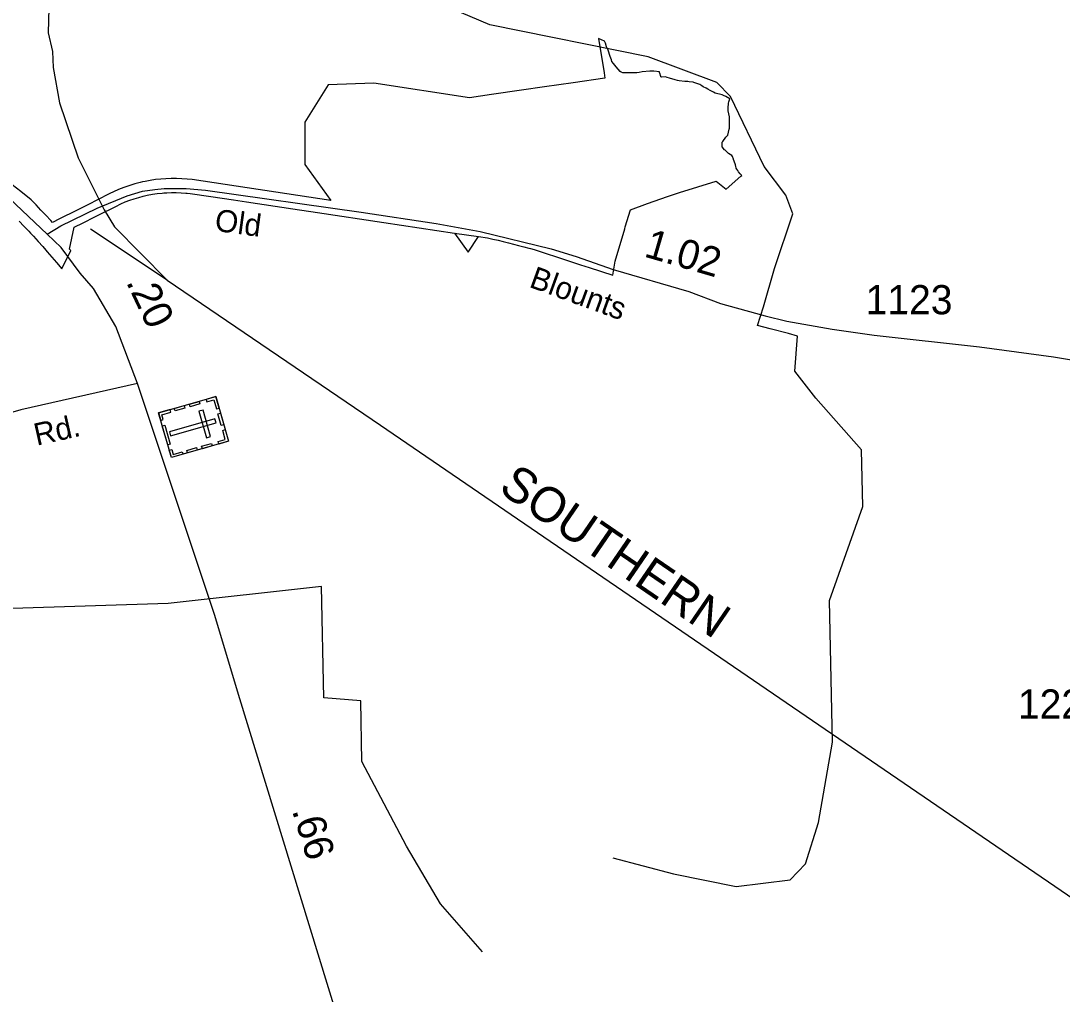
# Model space of a CAD drawing. Extents: x 2532689 to 2764727, y 536648 to 732970.
# Drawn here: x 2571899 to 2576359, y 639225 to 643394 of the extents above; entities that cross this region are included whole.
import ezdxf

# ---------------------------------------------------------------- set-up
doc = ezdxf.new("R2010")
doc.units = 0
for name, color, linetype in [('Exist Boundary Political City Limit New', 7, 'Continuous'), ('Exist Cultural Cemetery CELL', 7, 'Continuous'), ('Exist Hydrographic Creek Single Shore', 7, 'Continuous'), ('Exist Railroad Mainline', 7, 'Continuous'), ('Exist Railroad Mainline Label', 7, 'Continuous'), ('Exist Railroad Siding', 7, 'Continuous'), ('Exist Road Primary NC Attributed', 7, 'Continuous'), ('Exist Road Primary NC Mileage Hundredths English Label', 7, 'Continuous'), ('Exist Road Secondary Mileage Hundredths English Label', 7, 'Continuous'), ('Exist Road Secondary Type 51 Attributed', 7, 'Continuous'), ('Exist Road Secondary Type 51 Label', 7, 'Continuous'), ('Exist Road Secondary Type 51 Number Label', 7, 'Continuous'), ('Map Preparation Boundary City Limit Buffer Line', 7, 'Continuous')]:
    doc.layers.add(name, color=color, linetype=linetype)

msp = doc.modelspace()

# ---------------------------------------------------------------- linework, layer by layer
at = {"layer": 'Exist Boundary Political City Limit New'}
for points in [[(2574743.5, 643134.7), (2574718.8, 643136.3), (2574711, 643138.3), (2574702, 643141.1), (2574677, 643148.3), (2574667, 643151.5), (2574660.8, 643153.9), (2574644, 643153.1), (2574640.2, 643153.9), (2574639.8, 643155.4), (2574636.2, 643169.1), (2574635, 643171.5), (2574634.2, 643175.9), (2574610.2, 643177.9), (2574592.8, 643178.3), (2574560, 643175.1), (2574546.8, 643172.3), (2574537.8, 643171.5), (2574501.5, 643170.8), (2574495.5, 643171.5), (2574476.8, 643171.5), (2574469.8, 643174.3), (2574466.2, 643177.1), (2574448.8, 643196.8), (2574437.5, 643211.6), (2574430.8, 643219.9), (2574429, 643227.1), (2574426.2, 643234.3), (2574423.8, 643241.1), (2574414.8, 643267.9), (2574407.5, 643281.9), (2574403, 643297.9), (2574399.5, 643306.8), (2574373.8, 643318.1), (2574396.8, 643170.5), (2574400.2, 643148.5), (2574265, 643128.8), (2574141.2, 643110.8), (2574043.2, 643096.4), (2573915.5, 643077.8), (2573821.2, 643064.1), (2573411, 643126.2), (2573214.5, 643119.8), (2573115.2, 642959.4), (2573115.2, 642778.2), (2573227, 642624.7), (2572632.2, 642713.8), (2572610.5, 642716.2), (2572588.2, 642717.8), (2572565.5, 642718.7), (2572543, 642718.7), (2572520.2, 642717.8), (2572498, 642716.2), (2572475.8, 642713.7), (2572453.2, 642710.4), (2572431.2, 642706.2), (2572420.2, 642703.8), (2572409.2, 642701.4), (2572387.2, 642695.6), (2572365.8, 642689.1), (2572344.5, 642681.8), (2572323.5, 642673.8), (2572301.5, 642664.8), (2572274.2, 642651), (2572185, 642606), (2572136.8, 642581.8), (2572064.8, 642545.6), (2572034.2, 642530.2), (2572026.8, 642538.4), (2572005.8, 642560.9), (2571984.8, 642583.2), (2571963.8, 642605.2), (2571942.5, 642627.1), (2571898.8, 642663.1), (2571843, 642705.8)], [(2572624.5, 642654.6), (2572712.2, 642641.5), (2572809, 642627), (2572865.8, 642618.5), (2573064.2, 642588.8), (2573170.2, 642572.8), (2573453.5, 642530.4), (2573756, 642485.1), (2573814.6, 642403.5), (2573858.5, 642469.8), (2573898, 642463.8), (2573920.2, 642459), (2573942.8, 642454.1), (2573964.8, 642448.9), (2573987, 642443.6), (2574009, 642438), (2574031, 642432.2), (2574053, 642426.2), (2574075, 642420.1), (2574081.2, 642418.2), (2574097, 642413.8), (2574118.8, 642407.1), (2574140.5, 642400.3), (2574162.2, 642393.4), (2574181, 642387.2), (2574205.5, 642378.9), (2574214.2, 642375.8), (2574227, 642371.2), (2574253.2, 642362.7), (2574296.5, 642348.8), (2574333.2, 642336.9), (2574434, 642304.2), (2574444, 642364.3), (2574485.5, 642503.7), (2574488, 642511.4), (2574509.8, 642584.6), (2574583.2, 642611.1), (2574668.5, 642641.8), (2574694.8, 642650.4), (2574719.5, 642658.1), (2574876.8, 642706.6), (2574920.5, 642672.6), (2574982.8, 642728.3), (2574986.5, 642732.1), (2574980, 642738.6), (2574972.8, 642747), (2574971.5, 642749.4), (2574969.5, 642752.2), (2574966, 642758.2), (2574962.8, 642763), (2574960.8, 642771.4), (2574960.5, 642774.6), (2574960.5, 642776.6), (2574958, 642781), (2574950.8, 642799.4), (2574950.8, 642801.8), (2574947.5, 642813), (2574944, 642816.6), (2574930.5, 642825.8), (2574928.8, 642827.4), (2574915.5, 642840.2), (2574913.2, 642841.4), (2574903.2, 642853.8), (2574903.2, 642855.8), (2574903.2, 642861.8), (2574903.5, 642873.8), (2574905.2, 642877.4), (2574918.8, 642896.2), (2574923.5, 642900.6), (2574926.5, 642904.2), (2574933.2, 642929.9), (2574934, 642934.2), (2574934, 642968.2), (2574934.8, 642976.7), (2574934, 642983.4), (2574929.2, 643008.7), (2574928.5, 643011.9), (2574928, 643021.5), (2574929.5, 643040.3), (2574930, 643041.9), (2574931.5, 643047.5), (2574932.5, 643051.9), (2574935.2, 643059.9), (2574919.2, 643069.1), (2574908, 643074.3), (2574903.2, 643076.3), (2574873.5, 643084.3), (2574866, 643088.7), (2574863.5, 643090.3), (2574850.8, 643095.9), (2574842, 643100.7), (2574834, 643105.9), (2574821.5, 643111.5), (2574816.2, 643115.9), (2574807.5, 643121.5), (2574785.5, 643127.9), (2574781.5, 643130.3), (2574778, 643131.5), (2574762.2, 643133.1), (2574756, 643133.5), (2574743.5, 643134.7)], [(2571891.8, 642536), (2571912.2, 642514.4), (2571932.8, 642492.7), (2571940.5, 642484.2), (2571952.8, 642470.9), (2571972.8, 642448.9), (2571992.5, 642426.7), (2572005.8, 642411.8), (2572012.2, 642404.2), (2572031.8, 642381.8), (2572051, 642359.2), (2572073.8, 642331.8), (2572112.2, 642410.6), (2572107.5, 642416.2), (2572126.8, 642509.6), (2572165.8, 642529.2), (2572215.5, 642554.2), (2572233.5, 642563.2), (2572305.2, 642599.2), (2572326.8, 642609.9), (2572346, 642618.1), (2572365, 642625.4), (2572384.2, 642632), (2572403.8, 642637.9), (2572423.2, 642643), (2572439.2, 642646.6), (2572463.2, 642651.2), (2572483.2, 642654.2), (2572503.5, 642656.4), (2572511, 642657), (2572523.8, 642657.9), (2572544, 642658.7), (2572564.5, 642658.7), (2572584.8, 642657.9), (2572605, 642656.4), (2572611.5, 642655.8), (2572624.5, 642654.6)]]:
    msp.add_lwpolyline(points, dxfattribs=at)
at = {"layer": 'Exist Cultural Cemetery CELL'}
for points in [[(2572733.6, 641784.5), (2572788.3, 641593.1), (2572543.5, 641523.1), (2572488.8, 641714.5)], [(2572620.7, 641752.2), (2572662.3, 641764.1), (2572665.4, 641753.2), (2572623.8, 641741.3)], [(2572692, 641772.6), (2572695.1, 641761.7), (2572726, 641770.5), (2572737.2, 641731.5), (2572747.9, 641734.6), (2572733.6, 641784.5)], [(2572497.9, 641682.7), (2572509, 641685.9), (2572502.9, 641707), (2572541.8, 641718.1), (2572538.7, 641728.8), (2572488.8, 641714.6)], [(2572556, 641733.7), (2572597.7, 641745.7), (2572600.8, 641734.7), (2572559.2, 641722.8)], [(2572679.4, 641726.5), (2572661.4, 641721.4), (2572693.8, 641608.2), (2572711.8, 641613.3)], [(2572754, 641713.3), (2572768.2, 641663.4), (2572757.2, 641660.3), (2572743, 641710.1)], [(2572735.4, 641671.6), (2572730.3, 641689.6), (2572535.3, 641633.8), (2572540.4, 641615.9)], [(2572515.6, 641662.4), (2572539, 641580.8), (2572528, 641577.7), (2572504.7, 641659.3)], [(2572746.7, 641581.1), (2572743.6, 641592), (2572774.5, 641600.9), (2572763.3, 641639.8), (2572774, 641642.9), (2572788.3, 641593)], [(2572673.3, 641572), (2572714.9, 641583.9), (2572718.1, 641572.9), (2572676.4, 641561)], [(2572534.4, 641554.9), (2572545.5, 641558.1), (2572551.5, 641536.9), (2572590.4, 641548), (2572593.4, 641537.3), (2572543.5, 641523.1)], [(2572609.9, 641553.9), (2572651.5, 641565.8), (2572654.7, 641554.8), (2572613, 641542.9)]]:
    msp.add_lwpolyline(points, close=True, dxfattribs=at)
at = {"layer": 'Exist Hydrographic Creek Single Shore'}
for points in [[(2575205.4, 642567.5), (2575176.3, 642646.9), (2575082.6, 642770.3), (2574939.3, 643070.2), (2574879.4, 643130.2), (2574585.4, 643239.8), (2573908.3, 643376.5), (2573739.3, 643448.5), (2573680.3, 643521.6), (2573670.2, 643580.3), (2573781.4, 644316.9), (2573769.3, 644500.3)], [(2574434.4, 639809.4), (2574694.4, 639741.1), (2574962.5, 639686.2), (2575194.4, 639715.3), (2575260.4, 639783.7), (2575315.3, 639959.9), (2575375.4, 640303.7), (2575363.3, 640910.6), (2575505.4, 641313.7), (2575500.3, 641556.4), (2575304.3, 641778.3), (2575214.5, 641893.7), (2575226.2, 642043.3), (2575187.7, 642054.2), (2575108.1, 642074.8), (2575053.9, 642088.6), (2575080, 642168.8), (2575127, 642333.2), (2575205.4, 642567.5)], [(2573876.3, 639405.9), (2573696.3, 639612.1), (2573550.3, 639859), (2573359.4, 640222.2), (2573355.3, 640481.4), (2573196.3, 640494.7), (2573187.3, 640970.4), (2572530.3, 640897.8), (2571863.3, 640877.4), (2571276.2, 640646.8), (2570830.2, 640454.8), (2570515.3, 640382.9), (2570213.2, 640469.2), (2569689.3, 640392.2), (2569532.3, 640356.3), (2569356.3, 640368.9), (2569290.3, 640385.9), (2569145.3, 640547.4), (2569086.3, 640555)]]:
    msp.add_lwpolyline(points, dxfattribs=at)
at = {"layer": 'Exist Railroad Mainline'}
for points in [[(2575421.1, 650070.8), (2573243.7, 646762), (2573108.4, 646521.5), (2572995.4, 646263.1), (2572077.2, 643803.1), (2572051.1, 643718.6), (2572018.3, 643448.1), (2572016.4, 643342), (2572034.1, 643262.3), (2572037.1, 643194.4), (2572064.3, 643042.9), (2572144.8, 642806.4), (2572255.2, 642584.7), (2572300.5, 642511.4), (2572525.8, 642282.5)], [(2572525.8, 642282.5), (2573440, 641662.2), (2577952.7, 638576.3), (2579703.9, 637398.6), (2582102.3, 635741.4), (2582438.6, 635518), (2583142.3, 635027.7), (2583469.8, 634748.1), (2583588.6, 634602.5), (2583693.8, 634446.5), (2585802.7, 630027.3), (2588116.1, 625046), (2589599.7, 621904.9), (2590594.5, 619826.2), (2591961.9, 616896.7), (2592296.1, 616165.2), (2592491.3, 615704.9), (2592550.7, 615536), (2592632.4, 615243.8), (2592711.2, 614781.1), (2592925.5, 613761.1), (2593409.6, 611304.5), (2593932.6, 608794.3)]]:
    msp.add_lwpolyline(points, dxfattribs=at)
at = {"layer": 'Exist Railroad Siding'}
msp.add_line((2572525.8, 642282.5), (2572197.5, 642501.9), dxfattribs=at)
at = {"layer": 'Exist Road Primary NC Attributed'}
for points in [[(2572011.7, 642480.6), (2571850.1, 642632.6), (2571779.4, 642689.9), (2571699.8, 642745.8), (2571246.3, 643068.4)], [(2572398.3, 641840), (2572305, 642085.3), (2572210, 642247), (2572152.9, 642313.6), (2572072.1, 642423), (2572011.7, 642480.6)], [(2573437.1, 638535.8), (2572837.5, 640489.8), (2572728.1, 640851.3), (2572398.3, 641840)]]:
    msp.add_lwpolyline(points, dxfattribs=at)
at = {"layer": 'Exist Road Secondary Type 51 Attributed'}
for points in [[(2572011.7, 642480.6), (2572070, 642515.6), (2572225.5, 642591), (2572354.5, 642644.2), (2572419.7, 642664.1), (2572472.5, 642671.7), (2572512.3, 642675.5), (2572607.3, 642675.5), (2572690.1, 642668.8), (2573357.2, 642574.7), (2573677.3, 642525.7), (2573866.7, 642491.4), (2574171.1, 642416.9), (2574276.8, 642384.7), (2574436.5, 642329.4), (2574759.7, 642234.3), (2574896.4, 642183.6), (2575086.5, 642130.1), (2575180.2, 642107.1), (2575374.4, 642072.8), (2575554.4, 642047.8), (2576004.7, 641996.9), (2576322.4, 641954.4), (2576477.2, 641928.7)], [(2572398.3, 641840), (2571898.5, 641728.2), (2571763.1, 641688.5), (2571668, 641631.4), (2571501.2, 641534), (2571281.4, 641423.6), (2570650.6, 641198.6), (2569766.3, 640884.6)]]:
    msp.add_lwpolyline(points, dxfattribs=at)
at = {"layer": 'Map Preparation Boundary City Limit Buffer Line'}
for points in [[(2574743.5, 643134.7), (2574718.8, 643136.3), (2574711, 643138.3), (2574702, 643141.1), (2574677, 643148.3), (2574667, 643151.5), (2574660.8, 643153.9), (2574644, 643153.1), (2574640.2, 643153.9), (2574639.8, 643155.4), (2574636.2, 643169.1), (2574635, 643171.5), (2574634.2, 643175.9), (2574610.2, 643177.9), (2574592.8, 643178.3), (2574560, 643175.1), (2574546.8, 643172.3), (2574537.8, 643171.5), (2574501.5, 643170.8), (2574495.5, 643171.5), (2574476.8, 643171.5), (2574469.8, 643174.3), (2574466.2, 643177.1), (2574448.8, 643196.8), (2574437.5, 643211.6), (2574430.8, 643219.9), (2574429, 643227.1), (2574426.2, 643234.3), (2574423.8, 643241.1), (2574414.8, 643267.9), (2574407.5, 643281.9), (2574403, 643297.9), (2574399.5, 643306.8), (2574373.8, 643318.1), (2574396.8, 643170.5), (2574400.2, 643148.5), (2574265, 643128.8), (2574141.2, 643110.8), (2574043.2, 643096.4), (2573915.5, 643077.8), (2573821.2, 643064.1), (2573411, 643126.2), (2573214.5, 643119.8), (2573115.2, 642959.4), (2573115.2, 642778.2), (2573227, 642624.7), (2572632.2, 642713.8), (2572610.5, 642716.2), (2572588.2, 642717.8), (2572565.5, 642718.7), (2572543, 642718.7), (2572520.2, 642717.8), (2572498, 642716.2), (2572475.8, 642713.7), (2572453.2, 642710.4), (2572431.2, 642706.2), (2572420.2, 642703.8), (2572409.2, 642701.4), (2572387.2, 642695.6), (2572365.8, 642689.1), (2572344.5, 642681.8), (2572323.5, 642673.8), (2572301.5, 642664.8), (2572274.2, 642651), (2572185, 642606), (2572136.8, 642581.8), (2572064.8, 642545.6), (2572034.2, 642530.2), (2572026.8, 642538.4), (2572005.8, 642560.9), (2571984.8, 642583.2), (2571963.8, 642605.2), (2571942.5, 642627.1), (2571898.8, 642663.1), (2571843, 642705.8)], [(2572624.5, 642654.6), (2572712.2, 642641.5), (2572809, 642627), (2572865.8, 642618.5), (2573064.2, 642588.8), (2573170.2, 642572.8), (2573453.5, 642530.4), (2573756, 642485.1), (2573858.5, 642469.8), (2573898, 642463.8), (2573920.2, 642459), (2573942.8, 642454.1), (2573964.8, 642448.9), (2573987, 642443.6), (2574009, 642438), (2574031, 642432.2), (2574053, 642426.2), (2574075, 642420.1), (2574081.2, 642418.2), (2574097, 642413.8), (2574118.8, 642407.1), (2574140.5, 642400.3), (2574162.2, 642393.4), (2574181, 642387.2), (2574205.5, 642378.9), (2574214.2, 642375.8), (2574227, 642371.2), (2574253.2, 642362.7), (2574296.5, 642348.8), (2574333.2, 642336.9), (2574434, 642304.2), (2574444, 642364.3), (2574485.5, 642503.7), (2574488, 642511.4), (2574509.8, 642584.6), (2574583.2, 642611.1), (2574668.5, 642641.8), (2574694.8, 642650.4), (2574719.5, 642658.1), (2574876.8, 642706.6), (2574920.5, 642672.6), (2574982.8, 642728.3), (2574986.5, 642732.1), (2574980, 642738.6), (2574972.8, 642747), (2574971.5, 642749.4), (2574969.5, 642752.2), (2574966, 642758.2), (2574962.8, 642763), (2574960.8, 642771.4), (2574960.5, 642774.6), (2574960.5, 642776.6), (2574958, 642781), (2574950.8, 642799.4), (2574950.8, 642801.8), (2574947.5, 642813), (2574944, 642816.6), (2574930.5, 642825.8), (2574928.8, 642827.4), (2574915.5, 642840.2), (2574913.2, 642841.4), (2574903.2, 642853.8), (2574903.2, 642855.8), (2574903.2, 642861.8), (2574903.5, 642873.8), (2574905.2, 642877.4), (2574918.8, 642896.2), (2574923.5, 642900.6), (2574926.5, 642904.2), (2574933.2, 642929.9), (2574934, 642934.2), (2574934, 642968.2), (2574934.8, 642976.7), (2574934, 642983.4), (2574929.2, 643008.7), (2574928.5, 643011.9), (2574928, 643021.5), (2574929.5, 643040.3), (2574930, 643041.9), (2574931.5, 643047.5), (2574932.5, 643051.9), (2574935.2, 643059.9), (2574919.2, 643069.1), (2574908, 643074.3), (2574903.2, 643076.3), (2574873.5, 643084.3), (2574866, 643088.7), (2574863.5, 643090.3), (2574850.8, 643095.9), (2574842, 643100.7), (2574834, 643105.9), (2574821.5, 643111.5), (2574816.2, 643115.9), (2574807.5, 643121.5), (2574785.5, 643127.9), (2574781.5, 643130.3), (2574778, 643131.5), (2574762.2, 643133.1), (2574756, 643133.5), (2574743.5, 643134.7)], [(2571891.8, 642536), (2571912.2, 642514.4), (2571932.8, 642492.7), (2571940.5, 642484.2), (2571952.8, 642470.9), (2571972.8, 642448.9), (2571992.5, 642426.7), (2572005.8, 642411.8), (2572012.2, 642404.2), (2572031.8, 642381.8), (2572051, 642359.2), (2572073.8, 642331.8), (2572112.2, 642410.6), (2572107.5, 642416.2), (2572126.8, 642509.6), (2572165.8, 642529.2), (2572215.5, 642554.2), (2572233.5, 642563.2), (2572305.2, 642599.2), (2572326.8, 642609.9), (2572346, 642618.1), (2572365, 642625.4), (2572384.2, 642632), (2572403.8, 642637.9), (2572423.2, 642643), (2572439.2, 642646.6), (2572463.2, 642651.2), (2572483.2, 642654.2), (2572503.5, 642656.4), (2572511, 642657), (2572523.8, 642657.9), (2572544, 642658.7), (2572564.5, 642658.7), (2572584.8, 642657.9), (2572605, 642656.4), (2572611.5, 642655.8), (2572624.5, 642654.6)]]:
    msp.add_lwpolyline(points, dxfattribs=at)

# ---------------------------------------------------------------- texts
at = {"layer": 'Exist Railroad Mainline Label'}
msp.add_text('SOUTHERN', height=150, rotation=325.5754, dxfattribs=at).set_placement((2573939.8, 641379.9))
at = {"layer": 'Exist Road Primary NC Mileage Hundredths English Label'}
for s, rotation, p in [('.20', 295.3125, (2572347.9, 642275.9)), ('.66', 287.0597, (2573059.4, 640012))]:
    msp.add_text(s, height=125, rotation=rotation, dxfattribs=at).set_placement(p)
at = {"layer": 'Exist Road Secondary Mileage Hundredths English Label'}
msp.add_text('1.02', height=125, rotation=343.7604, dxfattribs=at).set_placement((2574564, 642385.3))
at = {"layer": 'Exist Road Secondary Type 51 Label'}
for s, rotation, p in [('Old', 352.2803, (2572725.9, 642495)), ('Blounts', 339.9918, (2574071.9, 642255.2)), ('Rd.', 12.6115, (2571966.6, 641573.8))]:
    msp.add_text(s, height=95, rotation=rotation, dxfattribs=at).set_placement(p)
at = {"layer": 'Exist Road Secondary Type 51 Number Label'}
for s, p in [('1123', (2575517.6, 642137.4)), ('1228', (2576169.7, 640405.5))]:
    msp.add_text(s, height=125, rotation=359.94, dxfattribs=at).set_placement(p)

doc.saveas('drawing.dxf')
